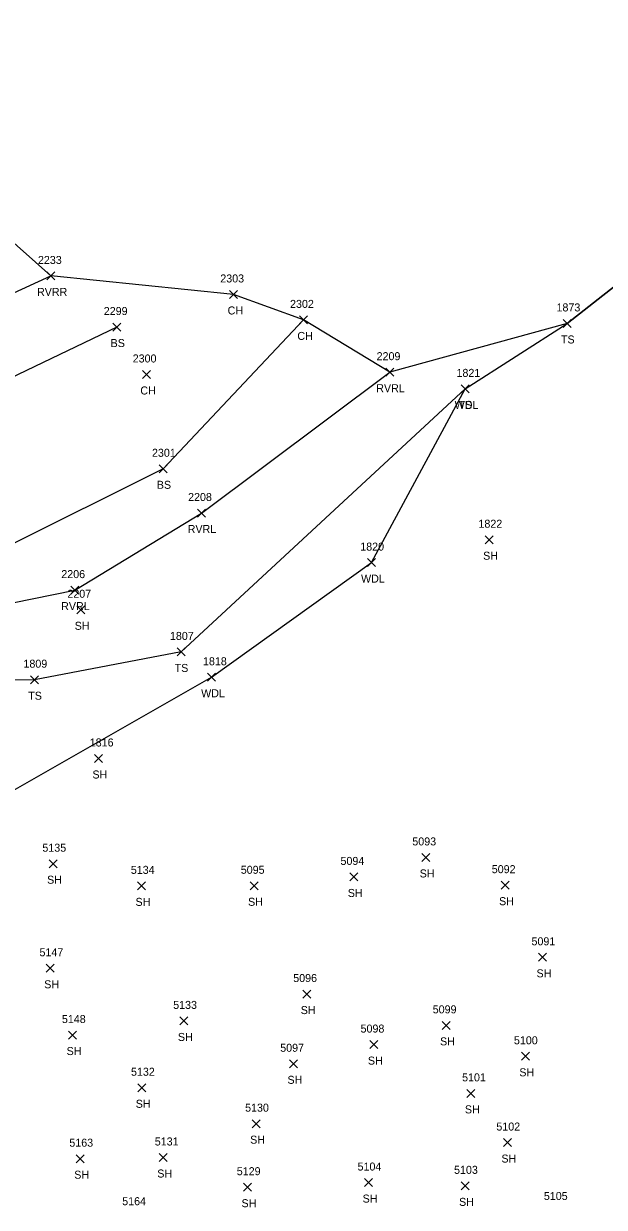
# Model space of a CAD drawing. Extents: x 1509053 to 1511576, y 400838 to 402572.
# Drawn here: x 1510136.1 to 1510281.3, y 401737.5 to 402033.2 of the extents above; entities that cross this region are included whole.
import ezdxf

# ---------------------------------------------------------------- set-up
doc = ezdxf.new("R2010")
doc.units = 0
for name, color, linetype in [('L_A', 7, 'Continuous'), ('L_I', 7, 'Continuous'), ('L_TIC', 7, 'Continuous'), ('LAWA', 7, 'Continuous'), ('LAWE', 7, 'Continuous'), ('LELB', 7, 'Continuous'), ('LSOGP', 7, 'Continuous')]:
    doc.layers.add(name, color=color, linetype=linetype)

msp = doc.modelspace()

# ---------------------------------------------------------------- linework, layer by layer
at = {"layer": 'L_TIC'}
for points in [[(1510141.92, 401969.2), (1510143.92, 401971.2)], [(1510143.92, 401969.2), (1510141.92, 401971.2)], [(1510187.59, 401964.57), (1510189.59, 401966.57)], [(1510189.59, 401964.57), (1510187.59, 401966.57)], [(1510205.03, 401958.21), (1510207.03, 401960.21)], [(1510207.03, 401958.21), (1510205.03, 401960.21)], [(1510271.01, 401957.33), (1510273.01, 401959.33)], [(1510273.01, 401957.33), (1510271.01, 401959.33)], [(1510158.39, 401956.43), (1510160.39, 401958.43)], [(1510160.39, 401956.43), (1510158.39, 401958.43)], [(1510165.77, 401944.58), (1510167.77, 401946.58)], [(1510167.77, 401944.58), (1510165.77, 401946.58)], [(1510226.67, 401945.15), (1510228.67, 401947.15)], [(1510228.67, 401945.15), (1510226.67, 401947.15)], [(1510245.43, 401940.98), (1510247.43, 401942.98)], [(1510247.43, 401940.98), (1510245.43, 401942.98)], [(1510245.43, 401940.98), (1510247.43, 401942.98)], [(1510247.43, 401940.98), (1510245.43, 401942.98)], [(1510169.94, 401921.02), (1510171.94, 401923.02)], [(1510171.94, 401921.02), (1510169.94, 401923.02)], [(1510179.54, 401909.97), (1510181.54, 401911.97)], [(1510181.54, 401909.97), (1510179.54, 401911.97)], [(1510251.48, 401903.3), (1510253.48, 401905.3)], [(1510253.48, 401903.3), (1510251.48, 401905.3)], [(1510222.02, 401897.58), (1510224.02, 401899.58)], [(1510224.02, 401897.58), (1510222.02, 401899.58)], [(1510147.9, 401890.71), (1510149.9, 401892.71)], [(1510149.9, 401890.71), (1510147.9, 401892.71)], [(1510149.36, 401885.8), (1510151.36, 401887.8)], [(1510151.36, 401885.8), (1510149.36, 401887.8)], [(1510174.43, 401875.27), (1510176.43, 401877.27)], [(1510176.43, 401875.27), (1510174.43, 401877.27)], [(1510137.82, 401868.33), (1510139.82, 401870.33)], [(1510139.82, 401868.33), (1510137.82, 401870.33)], [(1510182.05, 401868.94), (1510184.05, 401870.94)], [(1510184.05, 401868.94), (1510182.05, 401870.94)], [(1510153.8, 401848.65), (1510155.8, 401850.65)], [(1510155.8, 401848.65), (1510153.8, 401850.65)], [(1510142.47, 401822.36), (1510144.47, 401824.36)], [(1510144.47, 401822.36), (1510142.47, 401824.36)], [(1510235.6, 401823.93), (1510237.6, 401825.93)], [(1510237.6, 401823.93), (1510235.6, 401825.93)], [(1510217.64, 401819.06), (1510219.64, 401821.06)], [(1510219.64, 401819.06), (1510217.64, 401821.06)], [(1510164.57, 401816.83), (1510166.57, 401818.83)], [(1510166.57, 401816.83), (1510164.57, 401818.83)], [(1510192.71, 401816.85), (1510194.71, 401818.85)], [(1510194.71, 401816.85), (1510192.71, 401818.85)], [(1510255.46, 401817), (1510257.46, 401819)], [(1510257.46, 401817), (1510255.46, 401819)], [(1510264.82, 401798.98), (1510266.82, 401800.98)], [(1510266.82, 401798.98), (1510264.82, 401800.98)], [(1510141.75, 401796.24), (1510143.75, 401798.24)], [(1510143.75, 401796.24), (1510141.75, 401798.24)], [(1510205.88, 401789.8), (1510207.88, 401791.8)], [(1510207.88, 401789.8), (1510205.88, 401791.8)], [(1510175.16, 401783.09), (1510177.16, 401785.09)], [(1510177.16, 401783.09), (1510175.16, 401785.09)], [(1510240.7, 401781.98), (1510242.7, 401783.98)], [(1510242.7, 401781.98), (1510240.7, 401783.98)], [(1510147.34, 401779.56), (1510149.34, 401781.56)], [(1510149.34, 401779.56), (1510147.34, 401781.56)], [(1510222.66, 401777.18), (1510224.66, 401779.18)], [(1510224.66, 401777.18), (1510222.66, 401779.18)], [(1510260.52, 401774.25), (1510262.52, 401776.25)], [(1510262.52, 401774.25), (1510260.52, 401776.25)], [(1510202.56, 401772.38), (1510204.56, 401774.38)], [(1510204.56, 401772.38), (1510202.56, 401774.38)], [(1510164.62, 401766.39), (1510166.62, 401768.39)], [(1510166.62, 401766.39), (1510164.62, 401768.39)], [(1510246.91, 401764.99), (1510248.91, 401766.99)], [(1510248.91, 401764.99), (1510246.91, 401766.99)], [(1510193.23, 401757.42), (1510195.23, 401759.42)], [(1510195.23, 401757.42), (1510193.23, 401759.42)], [(1510256.04, 401752.7), (1510258.04, 401754.7)], [(1510258.04, 401752.7), (1510256.04, 401754.7)], [(1510149.25, 401748.67), (1510151.25, 401750.67)], [(1510151.25, 401748.67), (1510149.25, 401750.67)], [(1510170, 401748.97), (1510172, 401750.97)], [(1510172, 401748.97), (1510170, 401750.97)], [(1510191.07, 401741.55), (1510193.07, 401743.55)], [(1510193.07, 401741.55), (1510191.07, 401743.55)], [(1510221.34, 401742.71), (1510223.34, 401744.71)], [(1510223.34, 401742.71), (1510221.34, 401744.71)], [(1510245.46, 401741.89), (1510247.46, 401743.89)], [(1510247.46, 401741.89), (1510245.46, 401743.89)]]:
    msp.add_lwpolyline(points, dxfattribs=at)
at = {"layer": 'LAWA'}
msp.add_lwpolyline([(1510104.92, 401847.34), (1510129.32, 401839.36), (1510183.05, 401869.94), (1510223.02, 401898.58), (1510246.43, 401941.98)], dxfattribs=at)
at = {"layer": 'LAWE'}
for points in [[(1510109.09, 401954.72), (1510122.14, 401960.72), (1510142.92, 401970.2)], [(1509916.21, 401807.74), (1509911.53, 401847.11), (1509926.07, 401866.24), (1509956.61, 401863.44), (1509979.11, 401873.51), (1510010.81, 401877.14), (1510057.8, 401877.09), (1510112.34, 401884.32), (1510148.9, 401891.71), (1510180.54, 401910.97), (1510227.67, 401946.15)]]:
    msp.add_lwpolyline(points, dxfattribs=at)
at = {"layer": 'LELB'}
for points in [[(1510159.39, 401957.43), (1510109.97, 401933.78), (1510073.83, 401925.83), (1510030.04, 401920.72), (1509978.38, 401922.31), (1509938.9, 401925.26), (1509910.2, 401929.61), (1509860.63, 401969.45), (1509838.12, 402012.73), (1509801.23, 402094.39), (1509783.45, 402152.2), (1509742.56, 402227.61), (1509676.33, 402272.85), (1509632.84, 402314.37), (1509578.95, 402339.23), (1509514.2, 402355.92), (1509451.14, 402377.68), (1509400.45, 402407.85), (1509346.01, 402449.55), (1509331.23, 402458.28), (1509283.72, 402454.96), (1509188.27, 402469.29), (1509186.96, 402469.12), (1509142.12, 402468.65)], [(1510246.43, 401941.98), (1510272.01, 401958.33), (1510331.98, 402005.35)], [(1510170.94, 401922.02), (1510206.03, 401959.21)], [(1510175.43, 401876.27), (1510246.43, 401941.98)], [(1510170.94, 401922.02), (1510131.39, 401902.24), (1510066.1, 401893.73), (1510027.13, 401887.71), (1509982.86, 401885.76), (1509940.36, 401876.17)], [(1510175.43, 401876.27), (1510138.82, 401869.33), (1510103.57, 401868.78), (1510083.56, 401864.66), (1510059.74, 401864.04), (1510015.18, 401864.81), (1509987.81, 401860.2)]]:
    msp.add_lwpolyline(points, dxfattribs=at)
at = {"layer": 'LSOGP'}
msp.add_lwpolyline([(1510331.98, 402005.35), (1510272.01, 401958.33), (1510227.67, 401946.15), (1510206.03, 401959.21), (1510188.59, 401965.57), (1510142.92, 401970.2), (1510122.15, 401988.62), (1510083.17, 402030.34), (1510073.21, 402023.55), (1510063.09, 401987.31), (1510035.33, 401975.1), (1510014.35, 401976.24), (1509972.96, 401975.8), (1509961.46, 401977.52), (1509928.84, 401979.54), (1509918.73, 401987.4), (1509907.05, 402022.55), (1509914.65, 402053.44)], dxfattribs=at)

# ---------------------------------------------------------------- texts
at = {"layer": 'L_A'}
for s, p in [('RVRR', (1510139.43, 401965.2)), ('CH', (1510187.08, 401960.57)), ('CH', (1510204.52, 401954.21)), ('BS', (1510157.83, 401952.43)), ('TS', (1510270.42, 401953.33)), ('CH', (1510165.26, 401940.58)), ('RVRL', (1510224.24, 401941.15)), ('WDL', (1510243.84, 401936.98)), ('TS', (1510244.83, 401936.98)), ('BS', (1510169.38, 401917.02)), ('RVRL', (1510177.1, 401905.97)), ('SH', (1510250.97, 401899.3)), ('WDL', (1510220.44, 401893.58)), ('RVRL', (1510145.46, 401886.71)), ('SH', (1510148.85, 401881.8)), ('TS', (1510173.84, 401871.27)), ('TS', (1510137.23, 401864.33)), ('WDL', (1510180.46, 401864.94)), ('SH', (1510153.29, 401844.65)), ('SH', (1510141.95, 401818.36)), ('SH', (1510235.09, 401819.93)), ('SH', (1510217.13, 401815.06)), ('SH', (1510164.06, 401812.83)), ('SH', (1510192.19, 401812.85)), ('SH', (1510254.95, 401813)), ('SH', (1510264.31, 401794.98)), ('SH', (1510141.23, 401792.24)), ('SH', (1510205.36, 401785.8)), ('SH', (1510174.65, 401779.09)), ('SH', (1510240.19, 401777.98)), ('SH', (1510146.83, 401775.56)), ('SH', (1510222.15, 401773.18)), ('SH', (1510202.05, 401768.38)), ('SH', (1510260.01, 401770.25)), ('SH', (1510164.11, 401762.39)), ('SH', (1510246.4, 401760.99)), ('SH', (1510192.72, 401753.42)), ('SH', (1510255.53, 401748.7)), ('SH', (1510148.74, 401744.67)), ('SH', (1510169.49, 401744.97)), ('SH', (1510220.83, 401738.71)), ('SH', (1510190.56, 401737.55)), ('SH', (1510244.95, 401737.89))]:
    msp.add_text(s, height=2, dxfattribs=at).set_placement(p)
at = {"layer": 'L_I'}
for s, p in [('2233', (1510139.66, 401973.19)), ('2303', (1510185.25, 401968.57)), ('2299', (1510156.12, 401960.43)), ('2302', (1510202.69, 401962.21)), ('1873', (1510269.31, 401961.33)), ('2300', (1510163.35, 401948.58)), ('2209', (1510224.33, 401949.15)), ('1821', (1510244.3, 401944.98)), ('1821', (1510244.3, 401944.98)), ('2301', (1510168.17, 401925.02)), ('2208', (1510177.2, 401913.97)), ('1822', (1510249.79, 401907.3)), ('1820', (1510220.24, 401901.58)), ('2206', (1510145.5, 401894.71)), ('2207', (1510147.02, 401889.8)), ('1807', (1510172.66, 401879.27)), ('1809', (1510136.04, 401872.33)), ('1818', (1510180.92, 401872.94)), ('1816', (1510152.62, 401852.65)), ('5093', (1510233.26, 401827.93)), ('5135', (1510140.77, 401826.36)), ('5094', (1510215.3, 401823.06)), ('5092', (1510253.12, 401821)), ('5134', (1510162.88, 401820.83)), ('5095', (1510190.37, 401820.85)), ('5091', (1510263.05, 401802.98)), ('5147', (1510140.05, 401800.24)), ('5096', (1510203.48, 401793.8)), ('5133', (1510173.47, 401787.09)), ('5099', (1510238.36, 401785.98)), ('5148', (1510145.65, 401783.56)), ('5098', (1510220.32, 401781.18)), ('5100', (1510258.66, 401778.25)), ('5097', (1510200.23, 401776.38)), ('5132', (1510162.93, 401770.39)), ('5101', (1510245.7, 401768.99)), ('5130', (1510191.45, 401761.42)), ('5102', (1510254.27, 401756.7)), ('5131', (1510168.87, 401752.97)), ('5163', (1510147.51, 401752.67)), ('5129', (1510189.37, 401745.55)), ('5104', (1510219.57, 401746.71)), ('5103', (1510243.69, 401745.89)), ('5105', (1510266.14, 401739.36)), ('5164', (1510160.73, 401738.05))]:
    msp.add_text(s, height=2, dxfattribs=at).set_placement(p)

doc.saveas('drawing.dxf')
